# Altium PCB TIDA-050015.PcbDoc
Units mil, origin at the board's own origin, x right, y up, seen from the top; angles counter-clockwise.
Board outline 1539 x 1310 mil, 4 copper layers (Top Layer, Signal Layer 1, Signal Layer 2, Bottom Layer), stack 61.6 mil thick; 64 components, 25 nets, 161 pads, 163 vias.
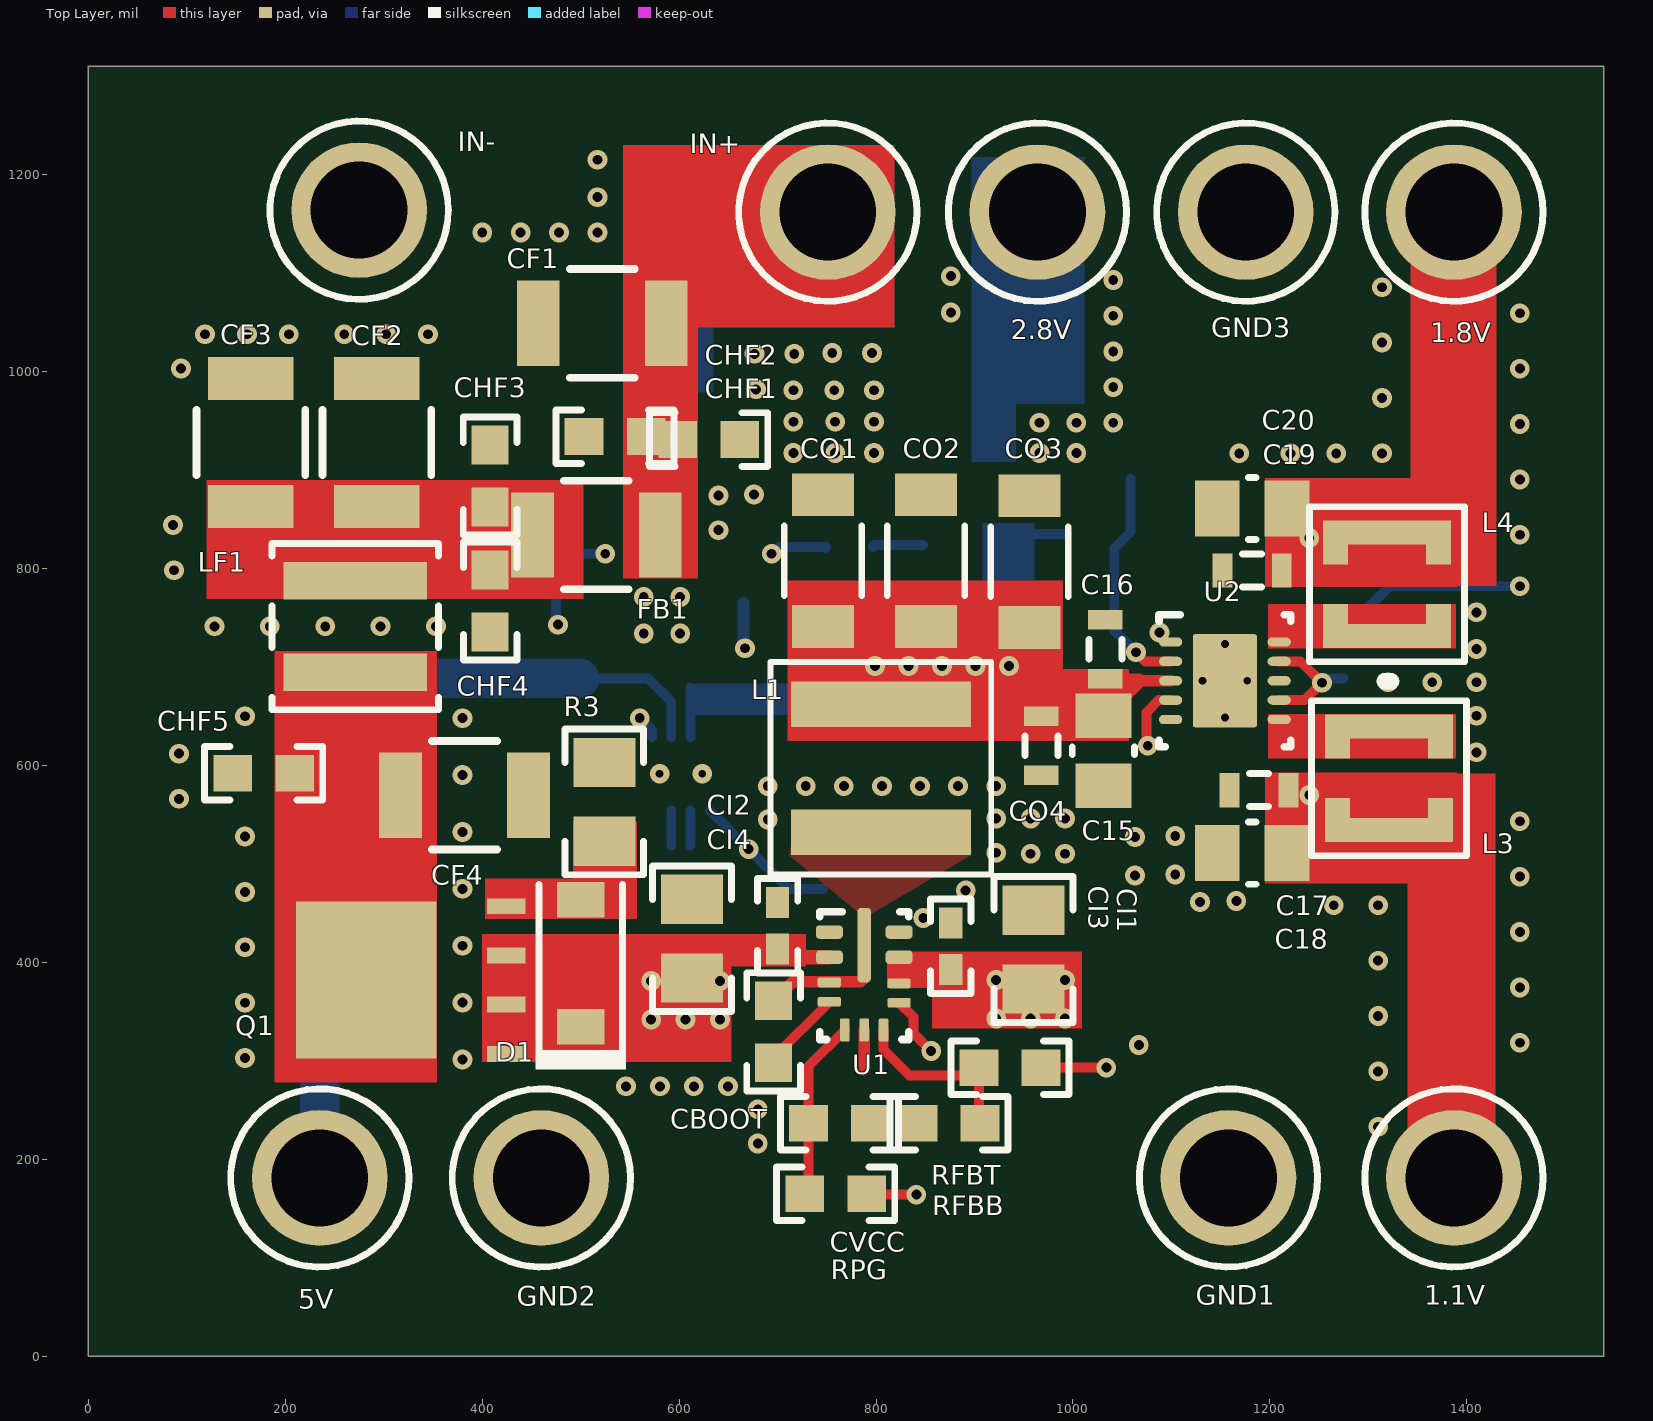
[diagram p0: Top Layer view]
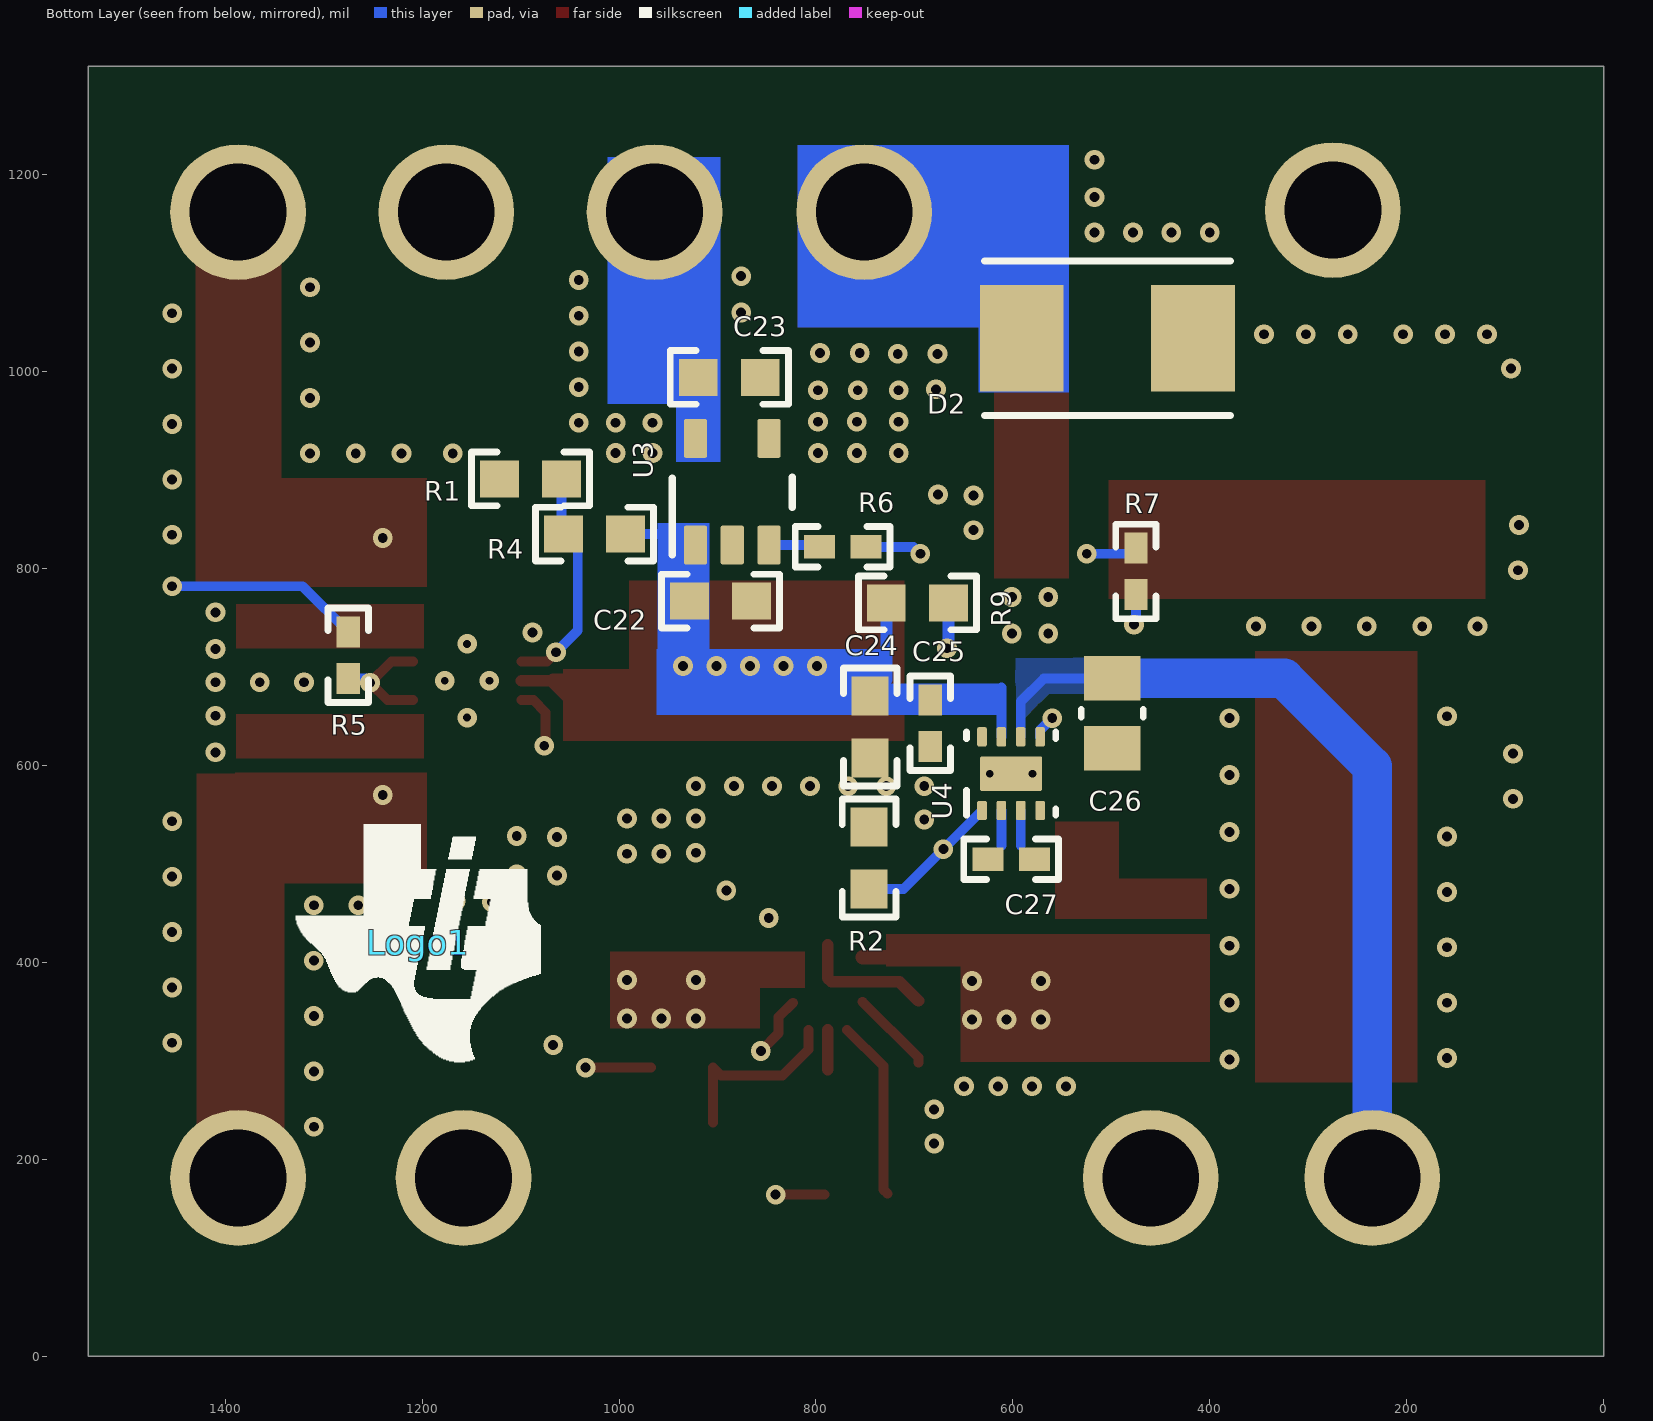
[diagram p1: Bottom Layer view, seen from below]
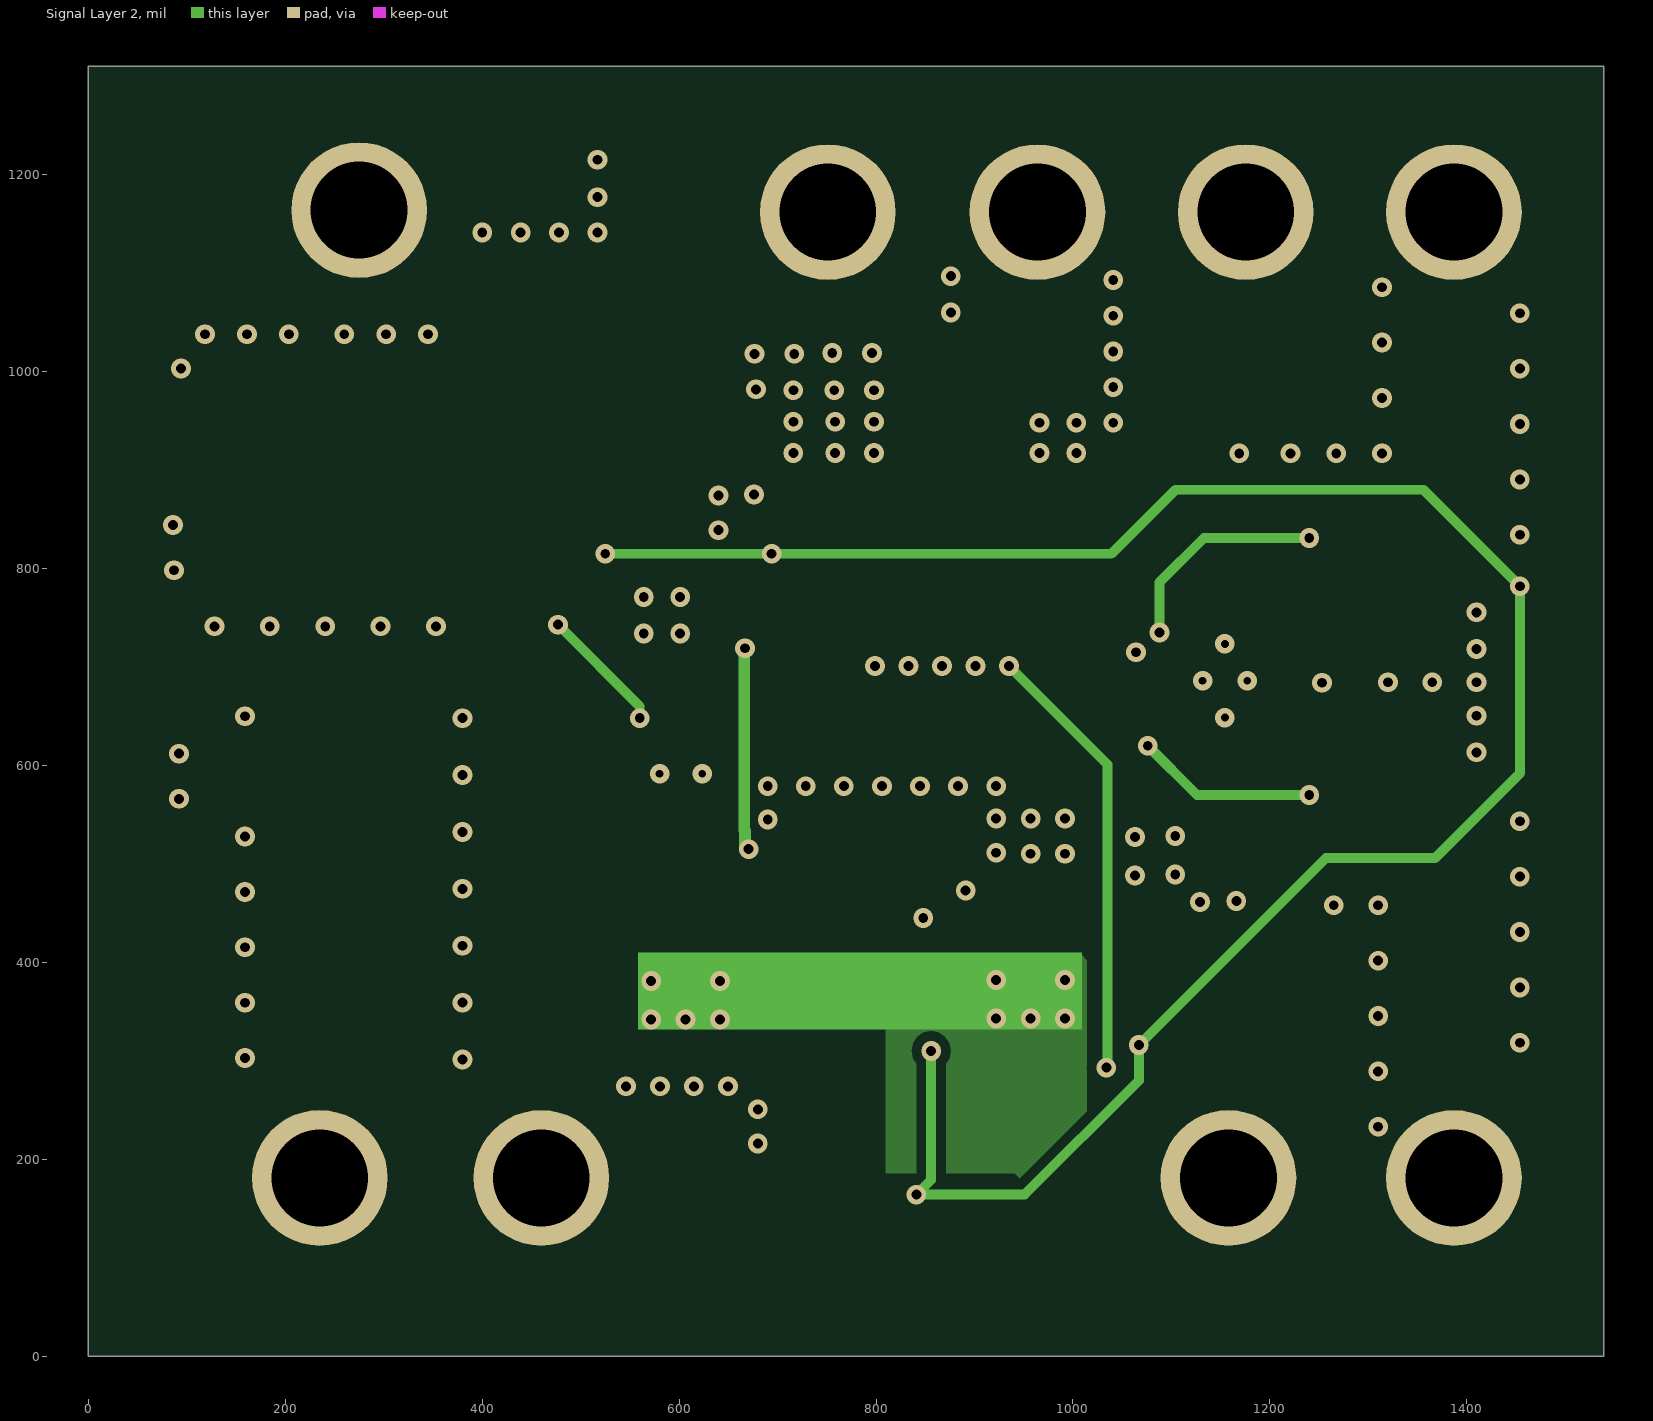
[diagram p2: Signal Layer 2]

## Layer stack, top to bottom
Top Solder: solder mask 0.4, Solder Resist, Dk 3.5
Top Layer: signal copper 1.4
Dielectric 1: prepreg 8, FR-4, Dk 4.2
Signal Layer 1: signal copper 1.4
Dielectric 2: core 40, FR-4, Dk 4.2
Signal Layer 2: signal copper 1.4
Dielectric 3: prepreg 8, FR-4, Dk 4.2
Bottom Layer: signal copper 1.4
Bottom Solder: solder mask 0.4, Solder Resist, Dk 3.5

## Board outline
0,0 1539,0 1539,1310 0,1310

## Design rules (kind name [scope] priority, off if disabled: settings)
AcuteAngle [All] p1: minimum=4.50000000000000E+0001 checktracksonly=FALSE
AssemblyTestPointUsage [All] p1: valid=2
BoardOutlineClearance BoardOutlineClearance_MountingHoles [OnCopper and InComponentClass('Mounting Holes')] p1: gap=40
BoardOutlineClearance BoardOutlineClearance_Poly [OnCopper and IsPoly] p2: gap=25
BoardOutlineClearance [OnCopper and Not InComponentClass('Logo') and not InComponentClass('FiducialMark') and not InRegion(1000,500,4000,800) and not InPoly] p3: gap=75
Clearance Clearance_Keepouts [((IsTrack Or IsArc) And Not InPoly) And IsFree and IsKeepOut vs ((IsTrack Or IsArc) And Not InPoly) And IsFree and IsKeepOut] p1: gap=0
Clearance Clearance_Poly [InPolygon] p2: gap=10
Clearance [All] p3: gap=7.87
ComponentClearance ComponentClearance_MountingHoles_FiducialMarks [InComponentClass('Mounting Holes') vs InComponentClass('FiducialMark')] p1: gap=50 collisioncheckmode=3 verticalgap=10 showdistances=FALSE
ComponentClearance ComponentClearance_Shunt [InComponentClass('Header') vs InComponentClass('Shunt')] p2: gap=0 collisioncheckmode=3 verticalgap=0 showdistances=FALSE
ComponentClearance ComponentClearance_Logo [InComponentClass('Logo')] p3: gap=50 collisioncheckmode=3 verticalgap=10 showdistances=FALSE
ComponentClearance ComponentClearance_ScrewToNut [(HasFootprint('NY PMS 440 0025 PH')) vs (HasFootprint('Keystone_1902C'))] p4: gap=5 collisioncheckmode=3 verticalgap=10 showdistances=FALSE
ComponentClearance ComponentClearance_MountingHoles [InComponentClass('Mounting Holes')] p5: gap=250 collisioncheckmode=3 verticalgap=100000 showdistances=FALSE
ComponentClearance ComponentClearance_SmallPassives [HasFootprint('0201*') or HasFootprint('0402*') or HasFootprint('0508') or HasFootprint('0603*') or HasFootprint('0612') or HasFootprint('0805*') or HasFootprint('0815*') or HasFootprint('0830*') or HasFootprint('1206*') or HasFootprint('1210*') or HasFootprint('1808*') or HasFootprint('1812*') or HasFootprint('1825*') or HasFootprint('2010*') or HasFootprint('2220*') or HasFootprint('2225*') or HasFootprint('2512*') or HasFootprint('2728*') or HasFootprint('3518*') vs HasFootprint('0201*') or HasFootprint('0402*') or HasFootprint('0508') or HasFootprint('0603*') or HasFootprint('0612') or HasFootprint('0805*') or HasFootprint('0815*') or HasFootprint('0830*') or HasFootprint('1206*') or HasFootprint('1210*') or HasFootprint('1808*') or HasFootprint('1812*') or HasFootprint('1825*') or HasFootprint('2010*') or HasFootprint('2220*') or HasFootprint('2225*') or HasFootprint('2512*') or HasFootprint('2728*') or HasFootprint('3518*')] p6: gap=14.96 collisioncheckmode=3 verticalgap=10 showdistances=FALSE
ComponentClearance ComponentClearance_THtoSMT [IsThruComponent vs IsSMTComponent] p7: gap=40 collisioncheckmode=3 verticalgap=30 showdistances=FALSE
ComponentClearance ComponentClearance_THtoTH [IsThruComponent vs IsThruComponent] p8: gap=30 collisioncheckmode=3 verticalgap=30 showdistances=FALSE
ComponentClearance [All] p9: gap=30 collisioncheckmode=3 verticalgap=10 showdistances=FALSE
DiffPairsRouting [All] p1: maxlimit=100 minlimit=10 mostfreqgap=10 toplayer_minwidth=15 toplayer_maxwidth=15 toplayer_prefwidth=15 midlayer1_minwidth=15 midlayer1_maxwidth=15 midlayer1_prefwidth=15 midlayer2_minwidth=15 midlayer2_maxwidth=15 midlayer2_prefwidth=15 bottomlayer_minwidth=15 bottomlayer_maxwidth=15 bottomlayer_prefwidth=15 maxuncoupledlength=1000
FabricationTestPointUsage TestPointUsage [All] p1: valid=2 allowmultiple=FALSE
FabricationTestpoint Testpoint [All] p1: side=3 testpointundercomponent=TRUE minsize=40 maxsize=100 preferedsize=60 minholesize=0 maxholesize=40 preferedholesize=32 testpointgrid=1 allowsidetop=TRUE allowsidebottom=TRUE usegrid=TRUE gridtolerance=0.01
FanoutControl Fanout_LCC [IsLCC] p1: bgadir=Out bgaviamode=Centered fanoutstyle=Auto fanoutdirection=Alternating viagrid=1 // Fanout_LCC (Default Rule)
FanoutControl Fanout_BGA [IsBGA] p2: bgadir=Out bgaviamode=Centered fanoutstyle=Auto fanoutdirection=Alternating viagrid=1 // Fanout_BGA (Default Rule)
FanoutControl Fanout_Default [All] p4: bgadir=Out bgaviamode=Centered fanoutstyle=Auto fanoutdirection=Alternating viagrid=1 // Fanout_Default (Default Rule)
FanoutControl Fanout_Small [(CompPinCount < 5)] p5: bgadir=Out bgaviamode=Centered fanoutstyle=Auto fanoutdirection=OutThenIn viagrid=1 // Fanout_Small (Default Rule)
HoleSize [All] p1: absolutevalues=TRUE maxlimit=251 minlimit=7.87 maxpercent=80.000 minpercent=20.000
MinimumAnnularRing MinimumAnnularRing_ThermalPadVias [IsVia and InAnyComponent] p1: minimumring=5.91
MinimumAnnularRing [All] p2: minimumring=8
MinimumSolderMaskSliver MinimumSolderMaskSliver_Logo [InComponentClass('Logo') vs InComponentClass('Logo')] p1: minsoldermaskwidth=0.7
MinimumSolderMaskSliver [All] p2: minsoldermaskwidth=3.94
PlaneConnect [All] p1: planeconnectstyle=Relief reliefexpansion=10 reliefentries=4 reliefconductorwidth=10 reliefairgap=10
PolygonConnect [All] p1: connectstyle=Direct reliefconductorwidth=10 reliefentries=4 polygonreliefangle="90 Angle" airgapwidth=10
RoutingVias ThermalPadVias [IsVia and InAnyComponent] p1: holewidth=7.87 width=19.68 viastyle="Through Hole" minholewidth=7.87 minwidth=19.68 maxholewidth=12.99 maxwidth=23.62
RoutingVias [All] p2: holewidth=16 width=34 viastyle="Through Hole" minholewidth=7.87 minwidth=26 maxholewidth=40 maxwidth=65
SilkToBoardRegionClearance [Not ((IsComment or IsDesignator) And (Hide <> 'False')) and not InRegion(1000,500,4000,800)] p1:
SilkToSilkClearance SilkToSilkClearance_Pb-FreeLogo [(HasFootprint('Pb-Free_Overlay_Medium') OR HasFootprint('Pb-Free_Overlay_Small')) vs (HasFootprint('Pb-Free_Overlay_Medium') OR HasFootprint('Pb-Free_Overlay_Small'))] p1: silktosilkclearance=0
SilkToSilkClearance [All] p2: silktosilkclearance=4
SilkToSolderMaskClearance SilkToComponentPadClearance [(IsPad or IsFill or IsRegion) and InAnycomponent] p1: minsilkscreentomaskgap=5 clearancetoexposedcopper=TRUE
SilkToSolderMaskClearance "Silk to Solder Mask Opening" [All] p2: minsilkscreentomaskgap=4 clearancetoexposedcopper=FALSE
SolderMaskExpansion [All] p1: expansion=1.97
Width [All] p1: maxlimit=100 minlimit=6 preferedwidth=10 checkconnectedcopper=TRUE
15 further rules are at their usual default settings.

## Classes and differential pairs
component class Logo: Logo1

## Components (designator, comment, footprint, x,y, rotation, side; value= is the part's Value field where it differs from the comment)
1.1V "Suggest using a net name here" Keystone1502-2 1387,181 r90 top
1.8V "Suggest using a net name here" Keystone1502-2 1387,1162 r90 top
2.8V "Suggest using a net name here" Keystone1502-2 964,1162 r90 top
5V "Suggest using a net name here" Keystone1502-2 235,181 r90 top
C15 "C2012X5R1A106M125AB" 0805_150 1031,615 r270 top
C16 "GCM188R71C104KA37J" 0603S 1033,718 r90 top
C17 "GCM188R71C104KA37J" 0603S 1189,575 r180 top
C18 "C2012X5R1A106M125AB" 0805_150 1182,511 r180 top
C19 "GCM188R71C104KA37J" 0603S 1182,798 r180 top
C20 "C2012X5R1A106M125AB" 0805_150 1182,861 r180 top
C22 "C0603C105K8PACTU" 0603 897,767 r0 bottom
C23 "GRM188R60J105KA01D" 0603 888,994 r180 bottom
C24 "C1608X5R1A106M080AC" 0603 745,639 r270 bottom
C25 "CL05A106MP5NUNC" 0402 684,643 r90 bottom
C26 "C2012X5R1A106M125AB" 0805_150 499,653 r270 bottom
C27 "C1005JB1V105K050BC" 0402 601.84,504.6 r0 bottom
CBOOT "0603YC104JAT2A" 0603 696,329.46 r90 top
CF1 "CGA6P3X7R1H475M250AB" 1210_280 522,1049 r180 top
CF2 "CGA6P3X7R1H475M250AB" 1210_280 293,928 r90 top
CF3 "CGA6P3X7R1H475M250AB" 1210_280 165,928 r90 top
CF4 "CGA6P3X7R1H475M250AB" 1210_280 382,569.74 r0 top
CHF1 "CGJ3E2X7R1C104K080AA" 0603 535,934 r180 top
CHF2 "CGJ3E2X7R1C104K080AA" 0603 630,931 r0 top
CHF3 "CGJ3E2X7R1C104K080AA" 0603 408,894 r90 top
CHF4 "CGJ3E2X7R1C104K080AA" 0603 408,767 r270 top
CHF5 "CGJ3E2X7R1C104K080AA" 0603 178,592 r180 top
CI1 "0805YD225KAT2A" 0805_HV 960,413 r90 top
CI2 "0805YD225KAT2A" 0805_HV 613,424 r270 top
CI3 "0402ZC103KAT2A" 0402 876,416.46 r90 top
CI4 "0402ZC103KAT2A" 0402 700,437 r90 top
CO1 "GRM31CR71A226KE15L" 1206_180 746,808 r270 top
CO2 "GRM31CR71A226KE15L" 1206_180 850.93,808 r270 top
CO3 "GRM31CR71A226KE15L" 1206_180 955.87,807 r270 top
CO4 "GCM188R71C104KA37J" 0603S 968,620 r270 top
CVCC "06033C105KAT2A" 0603 763,236.46 r0 top
D1 "MMSZ4705T1G" SOD-123 500,399 r90 top
D2 "1SMB30CAT3G" SMB-Bi 504,1034 r0 bottom
FB1 "FBMH3225HM601NT" 1210_280 516,834 r180 top
GND1 "Suggest using a net name here" Keystone1502-2 1158,181 r90 top
GND2 "Suggest using a net name here" Keystone1502-2 460,181 r90 top
GND3 "Suggest using a net name here" Keystone1502-2 1175.5,1162 r90 top
IN+ "Suggest using a net name here" Keystone1502-2 751,1162 r0 top
IN- "Suggest using a net name here" Keystone1502-2 275,1164 r0 top
L1 "XAL5030-222MEB" XAL5030 805,597 r90 top
L3 "LPS3015-222MLB" LPS3015 1321,587 r270 top
L4 "LPS3015-222MLB" LPS3015 1319,784 r90 top
LF1 "XAL4020-102MEB" XAL4020 271,741 r270 top
Logo1 "Texas Instruments" TI_Symbol_Overlay_Medium 1204,420 r180 bottom
Q1 "SQJ463EP-T1-GE3" PowerPAK_SO-8L 314,382 r180 top
R1 "CRCW06030000Z0EA" 0603 1090,891 r180 bottom
R2 "CRCW06030000Z0EA" 0603 746,506 r90 bottom
R3 "CRCW0805100KFKEA" 0805_HV 524,563 r270 top
R4 "CRCW06031M00FKEA" 0603 1025,835 r180 bottom
R5 "RC0402JR-070RL" 0402 1275,712 r270 bottom
R6 "RC0402JR-070RL" 0402 773,822 r0 bottom
R7 "RC0402JR-070RL" 0402 475,797 r270 bottom
R9 "CRCW06030000Z0EA" 0603 697,765 r180 bottom
RFBB "CRCW060334K8FKEA" 0603 874,236.46 r0 top
RFBT "CRCW0603100KFKEA" 0603 936,293 r0 top
RPG "CRCW0603100KFKEA" 0603 759,165 r0 top
U1 "LMR33630CRNXR" RNX0012A 788,386.46 r0 top
U2 "TPS62420DRCR" DRC0010J 1154.36,686 r0 top
U3 "LP5907MFX-2.8/NOPB" DBV0005A_N 885,878 r90 bottom
U4 "LM2775DSGR" DSG0008A 601.84,591.6 r90 bottom

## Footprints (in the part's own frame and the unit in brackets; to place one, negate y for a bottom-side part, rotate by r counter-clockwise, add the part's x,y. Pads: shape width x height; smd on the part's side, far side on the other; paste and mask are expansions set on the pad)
0402 [mm] "0402 from SM-752 data"
  rect 0.8x0.6 smd: 1(-0.6,0) 2(0.6,0)
  silkscreen extent -1.22,-0.52 1.22,0.52, body extent -0.55,-0.3 0.55,0.3, height 0.6
0603 [mm] "0603 from SM-752 data"
  rect 1x0.95 smd: 1(-0.8,0) 2(0.8,0)
  silkscreen extent -1.52,-0.69 1.52,0.69, body extent -0.87,-0.47 0.87,0.47, height 1
0603S [mil]
  rect 20x35 smd: 1(-30,0) 2(30,0)
  silkscreen extent -10,-17 10,17, body extent -34,-19 34,19, height 39
0805_150 [mm] "0805 / 1.5 mm height"
  rect 1.15x1.45 smd: 1(-0.9,0) 2(0.9,0)
  silkscreen extent -0.1,-0.8 0.1,0.8, body extent -1.1,-0.72 1.1,0.72, height 1.5
0805_HV [mil] "0805 with 30mil clearance between pads"
  rect 50x63 smd: 1(-40,0) 2(40,0)
  silkscreen extent -74,-40 74,40, body extent -43,-29 43,29, height 57
1206_180 [mm] "1206_180"
  rect 1.1x1.6 smd: 1(-1.7,0) 2(1.7,0)
  silkscreen extent -0.9,-1 0.9,1, body extent -1.75,-0.95 1.75,0.95, height 1.8
1210_280 [mm] "SMD, 2-Leads, Body 3.6x2.8mm, Height 2.8mm"
  rect 1.1x2.2 smd: 1(-1.65,0) 2(1.65,0)
  silkscreen extent -0.84,-1.4 0.84,1.4, body extent -1.8,-1.4 1.8,1.4, height 2.8
DBV0005A_N [mm] "SOT23, 5-Leads, Body 2.9x1.6mm, Pitch 0.95mm, Lead Span 2.8mm, IPC Medium Density"
  rrect17% 1x0.6 smd: 1(-1.375,0.95) 2(-1.375,0) 3(-1.375,-0.95) 4(1.375,-0.95) 5(1.375,0.95)
  silkscreen extent -1.63,-1.55 0.38,1.55, body extent -1.42,-1.46 1.42,1.46, height 1.09
DRC0010J [mm] "SON, 10-Leads, Body 3x3mm, Pitch 0.5mm, Thermal Pad 2.4x1.65mm, TI Recommended"
  rrect100% 0.6x0.24 smd: 1(-1.4,1) 2(-1.4,0.5) 3(-1.4,0) 4(-1.4,-0.5) 5(-1.4,-1) 6(1.4,-1) 7(1.4,-0.5) 8(1.4,0) 9(1.4,0.5) 10(1.4,1)
  rrect6% 1.65x2.4 smd paste-0.825: 11(0,0)
  silkscreen extent -1.7,-1.7 1.7,1.7, body extent -1.55,-1.55 1.55,1.55, height 1.01
DSG0008A [mm] "SON, 8-Leads, Body 2x2mm, Pitch 0.5mm, Thermal Pad 1.6x0.9mm, TI Recommended"
  rrect40% 0.5x0.25 smd: 1(-0.95,0.75) 2(-0.95,0.25) 3(-0.95,-0.25) 4(-0.95,-0.75) 5(0.95,-0.75) 6(0.95,-0.25) 7(0.95,0.25) 8(0.95,0.75)
  rrect14% 0.9x0.7 on Bottom Paste: 9(0,-0.45) 9(0,0.45)
  rrect11% 0.9x1.6 smd paste-0.45: 9(0,0)
  silkscreen extent -1.07,-1.15 1.07,1.15, body extent -1,-1 1,1, height 0.77
Keystone1502-2 [mm] "Double Turret"
  round 3.5 hole 2.5: 1(0,0)
  silkscreen extent -2.3,-2.3 2.3,2.3, body extent -1.6,-1.6 1.59,1.6, height 5.62
LPS3015 [mm] "Coilcraft recommended land pattern.  Document 436-2, rev 12/3/08"
  rect 0.63x3.3 smd: 1(-1.335,0) 2(1.335,0)
  rect 1.14x0.64 smd: 1(-1.08,1.33) 1(-1.08,-1.33) 2(1.08,1.33) 2(1.08,-1.33)
  silkscreen extent -2.59,-2 2,2, body extent -1.58,-1.58 1.58,1.58, height 1.52
PowerPAK_SO-8L [mm] "based on Vishay recommended land pattern Document 63818 Feb 7, 2012"
  rect 1x0.41 smd: 1(-2.805,1.905) 2(-2.805,0.635) 3(-2.805,-0.635) 4(-2.805,-1.905)
  rect 3.63x4.061 smd: 5(0.805,0)
  Top Layer region: -0.298,-2.64 0.298,-2.64 0.298,-2.03 -0.298,-2.03
  Top Layer region: -0.297,2.03 0.298,2.03 0.298,2.64 -0.297,2.64
  Top Layer region: 2.615,-2.5 3.125,-2.5 3.125,2.5 2.615,2.5
  body extent -3.07,-2.57 3.08,2.57, height 1.21
RNX0012A [mm]
  rrect57% 0.7x0.35 smd paste-0.05 mask-0.05: 1(-0.9,1.125) 2(-0.9,0.475) 10(0.9,0.475) 11(0.9,1.125)
  rrect40% 0.6x0.25 smd: 3(-0.9,-0.175) 4(-0.9,-0.675) 8(0.9,-0.7) 9(0.9,-0.2)
  rrect40% 0.25x0.6 smd: 5(-0.5,-1.4) 6(0,-1.4) 7(0.5,-1.4)
  rrect40% 0.25x0.812 on Top Paste: 12(0,0.28) 12(0,1.295)
  rrect57% 0.35x1.925 smd paste-0.175 mask-0.05: 12(0,0.788)
  silkscreen extent -1.15,-1.65 1.15,1.65, body extent -1.05,-1.55 1.05,1.55, height 1.02
SMB-Bi [mil] "Molded Diode, 2-Leads, Body 5.4x3.6mm, IPC Medium Density, based on OnSemi component dimensions"
  rect 85x107.99 smd: 1(-87.01,0) 2(87.01,0)
  silkscreen extent -125,-79 125,79, body extent -104,-73 104,73, height 89
SOD-123 [mm] "On Semi recommended land pattern"
  rect 0.915x1.22 smd: 1(-1.637,0) 2(1.637,0)
  silkscreen extent -2.74,-1.17 2.03,1.17, body extent -1.93,-0.9 1.93,0.9, height 1.35
TI_Symbol_Overlay_Medium [mil]
  silkscreen extent -124,-122 124,120
XAL4020 [mil] "Coilcraft XAL4020 7/18/12"
  rect 38x146 smd: 1(-46.5,0) 2(46.5,0)
  silkscreen extent -85,-85 85,85, body extent -84,-84 84,84, height 83
XAL5030 [mil] "Coilcraft XAL5030 12/12/11"
  rect 46x183 smd: 1(-65,0) 2(65,0)
  silkscreen extent -108,-112 108,112, body extent -108,-112 108,112, height 122

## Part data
1.1V 1.8V 2.8V 5V GND1 GND2 GND3 IN+ IN-: library part 1502-2, "Terminal, Turret, TH, Double"
C15 C18 C20 C26: "CAP, CERM, 10 µF, 10 V,+/- 20%, X5R, 0805"
C16 C17 C19 CHF1 CHF2 CHF3 CHF4 CHF5 CO4: "CAP, CERM, 0.1 µF, 16 V, +/- 10%, X7R, AEC-Q200 Grade 1, 0603"
C22: "CAP, CERM, 1 µF, 10 V,+/- 10%, X5R, 0603"
C23: "CAP, CERM, 1 µF, 6.3 V,+/- 10%, X5R, 0603"
C24: "CAP, CERM, 10 µF, 10 V,+/- 20%, X5R, 0603"
C25: "CAP, CERM, 10 µF, 10 V,+/- 20%, X5R, 0402"
C27: "CAP, CERM, 1 µF, 35 V,+/- 10%, JB, 0402"
CBOOT: "CAP, CERM, 0.1 µF, 16 V,+/- 5%, X7R, 0603"
CF1 CF2 CF3 CF4: "CAP, CERM, 4.7 µF, 50 V, +/- 20%, X7R, AEC-Q200 Grade 1, 1210"
CI1 CI2: "CAP, CERM, 2.2 µF, 16 V,+/- 10%, X5R, 0805"
CI3 CI4: "CAP, CERM, 0.01 µF, 10 V,+/- 10%, X7R, 0402"
CO1 CO2 CO3: "CAP, CERM, 22 µF, 10 V, +/- 10%, X7R, 1206"
CVCC: "CAP, CERM, 1 µF, 25 V,+/- 10%, X7R, 0603"
D1: "Diode, Zener, 18 V, 500 mW, SOD-123"
D2: "Diode, TVS, Bi, 30 V, 48.4 Vc, SMB"
FB1: "Ferrite Bead, 600 ohm @ 100 MHz, 3 A, 1210"
L1: "Inductor, Shielded, Composite, 2.2uH, 9.2A, 0.01 ohm, SMD"
L3 L4: "Inductor, Shielded Drum Core, Ferrite, 2.2uH, 1.4A, 0.11 ohm, SMD"
LF1: "Inductor, Shielded, Composite, 1uH, 8.75A, 0.01 ohm, SMD"
Logo1: library part TI_Logo, "Texas Instrument Corporate Signature"
Q1: "MOSFET, P-CH, -40 V, -30 A, PowerPAK_SO-8L"
R1 R2 R9: "RES, 0, 5%, 0.1 W, 0603"
R3: "RES, 100 k, 1%, 0.125 W, 0805"
R4: "RES, 1.00 M, 1%, 0.1 W, 0603"
R5 R6 R7: "RES, 0, 5%, 0.063 W, 0402"
RFBB: "RES, 34.8 k, 1%, 0.1 W, 0603"
RFBT RPG: "RES, 100 k, 1%, 0.1 W, 0603"
U1: "SIMPLE SWITCHER 3.8V to 36V 3A/2A Synchronous Step-Down Voltage Regulator, RNX0012A (VQFN-HR-12)"
U2: "Buck Adjustable Regulator with 2.5 to 6 V Input and 0.6 to 6 V Output, -40 to 85 degC, 10-Pin SON (DRC), Green (RoHS & no Sb/Br)"
U3: "250-mA Ultra-Low-Noise, Low-IQ LDO, DBV0005A (SOT-23-5)"
U4: "Switched Capacitor 5V Boost Converter, DSG0008A (WSON-8)"

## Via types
v1: diameter 20, hole 10, Top Layer to Bottom Layer, tented both sides, 144 vias
v2: diameter 20, hole 10, Top Layer to Bottom Layer, 13 vias
v3: diameter 19.68, hole 7.87, Top Layer to Bottom Layer, 6 vias

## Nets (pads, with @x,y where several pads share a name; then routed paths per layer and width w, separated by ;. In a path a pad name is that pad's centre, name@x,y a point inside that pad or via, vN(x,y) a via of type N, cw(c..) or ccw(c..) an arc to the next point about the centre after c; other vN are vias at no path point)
1.1V: 1.1V.1 C17.1 C18.1 L3.2 U2.4 | length 247
  Top Layer w10: v2@1074.56,621.44 1074.56,653.92 1086.95,666.32 U2.4
  Signal Layer 2 w10: v2(1076,620) 1126,570 v1(1240,570)
1.8V: 1.8V.1 C19.1 C20.1 L4.2 U2.1 | length 223.1
  Signal Layer 2 w10: v2@1089,734 v2(1088,735) 1088,786 1133,831 v1(1240,831)
3.3V: C15.1 C16.1 C22.2 C24.1 C25.2 CO1.2 CO2.2 CO3.2 CO4.1 L1.2 R4.2 R9.1 RFBT.2 U2.3 U3.1 U4.7 | length 828.1
  Top Layer w10: RFBT.2 v2(1034,293)
  Top Layer w12: 1066.57,686 U2.3
  Top Layer w15: C15.1 1066.57,686 C16.1@1035,686
  Signal Layer 2 w10: v1(935,701) 1035,601 1035,300 v2@1031,296
  Bottom Layer w10: U4.7 611.69,679.31 ; v1(799,701) 809,691 ; 937,835 R4.2
  Bottom Layer w12: C24.1@728.5,687 R9.1
  other v1: 833,701 867,701 901,701
5V: 5V.1 C26.1 U4.6 | length 857.8
  Bottom Layer w10: C26.1 568.57,688.43 592,665 U4.6
  Bottom Layer w40: 5V.1 235,599 324.43,688.43 C26.1
FB: RFBB.2 RFBT.1 U1.7 | length 186.6
  Top Layer w10: U1.7 807.68,311.32 834,285 896.5,285 RFBT.1 RFBB.2@904.5,237.45
GND: C15.2 C16.2 C17.2 C18.2 C19.2 C20.2 C22.1 C23.2 C24.2 C25.1 C26.2 CF1.2 CF2.2 CF3.2 CF4.2 CHF1.2 CHF2.2 CHF3.2 CHF4.2 CHF5.2 CI1.2 CI2.1 CI3.2 CI4.2 CO1.1 CO2.1 CO3.1 CO4.2 CVCC.2 D2.1 GND1.1 GND2.1 GND3.1 IN-.1 R1.1 R2.2 R3.1 RFBB.1 U1.1 U1.6 U1.11 U2.5 U2.8 U2.11 U3.2 U4.4 U4.8 U4.9@601.84,591.6 | length 40.3
  Top Layer w12: 788,291 U1.6
  other v1: 680,216 1310,233 680,250.67 546,274 580.67,274 615,274 649.67,274 1310,289.25 380,301.25 159,302.75 1454,318.25 1310,345.5 159,359 380,359.04 1454,374.5 1310,401.75 159,415.25 380,416.83 1454,430.75 848,445 1265,458 1310,458 1129,461.25 1166,462.25 159,471.5 891,473 380,474.62 1454,487 1063,488.25 1104,489.25 957,510.33 992,510.33 922,511.33 1063,527.25 159,527.75 1104,528.25 380,532.42 1454,543.25 690,545 922,546 957,546 992,546 92,566 690,579 728.67,579 767.33,579 806,579 844.67,579 883.33,579 922,579 380,590.21 92,612 1410,613.25 380,648 159,650 1410,650.5 1320,684.5 1365,684.5 1410,684.5 1410,718.25 564,734 601,734 128,741.25 184.25,741.25 240.5,741.25 296.75,741.25 353,741.25 1410,755.5 564,771 601,771 87,798.25 1454,834.25 640,839 86,844.25 640,874.25 676,875.25 1454,890.5 716,917.25 758.5,917.25 798,917.25 966,917.25 1003.5,917.25 1169,917 1221,917 1267.5,917 1314,917 1454,946.75 966,948 1003.5,948 1041,948 716,949.12 758.5,949.12 798,949.12 1314,973.25 716,981 757.5,981 798,981 678,982 1041,984.25 94,1003.25 1454,1003 676.5,1018 717,1018 755.5,1019 796,1019 1041,1020.5 1314,1029.5 118.4,1038 161,1038 203.6,1038 259.8,1038 302.4,1038 345,1038 1041,1056.75 1454,1059.25 876,1060 1314,1085.75 1041,1093 876,1097 400,1141.25 439,1141.25 478,1141.25 517,1141.25 517,1177.25 517,1215.25
  other v3: 580.19,591.6 623.5,591.6 1154.36,648.6 1131.72,686 1177,686 1154.36,723.4
MODE: R1.2 R4.1 U2.2 | length 231.1
  Top Layer w10: v2(1064,715) 1073.31,705.69 U2.2
  Bottom Layer w10: R1.2 1058.5,837.01 R4.1 1042,820.5 1042,737 v2(1064,715)
Net2.8V_1: 2.8V.1 C23.1 U3.5
NetC27_1: C27.1 U4.3 | length 35.8
  Bottom Layer w10: 592,518.38 U4.3
NetC27_2: C27.2 U4.2 | length 35.8
  Bottom Layer w10: 611.69,518.38 U4.2
NetCBOOT_1: CBOOT.1 U1.4 | length 85.4
  Top Layer w10: CBOOT.1 696,303.32 U1.4
NetCF1_1: CF1.1 CHF1.1 CHF2.1 D2.2 FB1.1 IN+.1
NetCF2_1: CF2.1 CF3.1 CHF3.1 CHF4.1 FB1.2 LF1.1
NetCF4_1: CF4.1 CHF5.1 LF1.2 Q1.5
NetD1_2: D1.2 Q1.4 R3.2 | length 69.1
  Top Layer w10: Q1.4 D1.2@493.53,457
NetL3_1: L3.1 U2.6
NetL4_1: L4.1 U2.10
NetR5_2: R5.2 U2.7 U2.9 | length 127.2
  Top Layer w10: U2.7 1235.32,666.32 v1(1253,684) 1231.31,705.69 U2.9
  Bottom Layer w10: v1(1253,684) 1257.38,688.38 R5.2
NetR6_2: R6.2 U3.3 | length 51.7
  Bottom Layer w10: R6.2 798.49,823.87 U3.3
NetR7_2: R7.2 U4.5 | length 181.9
  Signal Layer 2 w10: v2(477,743) 560,660 v2(560,648)
  Bottom Layer w10: v2@475,745 R7.2 ; v2(560,648) 572.32,635.68 U4.5
PFM: R2.1 R9.2 U4.1 | length 393.3
  Signal Layer 2 w12: v2@667,518.57 667,533.36 666.13,534.24 666.13,718.13 v2(667,719)
  Bottom Layer w10: U4.1 v2(670.57,515) 711.06,474.5 R2.1
  Bottom Layer w12: v2@665.5,720.5 R9.2
PG: R5.1 R6.1 R7.1 RPG.2 U1.8 | length 2572.2
  Top Layer w10: RPG.2@791.5,164 v2(841,164) ; U1.8 838,344.33 838,328 v2(856,310)
  Signal Layer 2 w10: v2(525,815) v2(694,815) 1039,815 1104,880 1356,880 v1(1454,782) 1454,592 1368,506 1257,506 v2(1067,316) 1067,280 951,164 v2(841,164) 856,179 v2(856,310)
  Bottom Layer w10: R7.1 480.62,815 v2(525,815) ; v2(694,815) 701,822 R6.1 R6.1@748.38,821 ; R5.1 1321.38,782 v1(1454,782)
SW: CBOOT.2 L1.1 U1.3 U1.12@788,417.48 | length 135
  Top Layer w12: CBOOT.2 715.22,380.18 784.18,380.18 788,384 U1.12@788,417.48
VCC: CVCC.1 RPG.1 U1.5 | length 183.2
  Top Layer w10: RPG.1 731.5,169 CVCC.1 731.5,294.53 U1.5
VIN: CI1.1 CI2.2 CI3.1 CI4.1 D1.1 Q1.1 Q1.2 Q1.3 U1.2 U1.9 U1.10 | length 118.4
  Top Layer w15: CI2.2@634.16,405.16 U1.2
  other v1: 571.54,342 606.54,342 641.54,342 922,343 957,343 992,343 571.54,381 641.54,381 922,382 992,382
pads on no net: U1.12@788,397.48 U1.12@788,437.44 U3.4 U4.9@584.13,591.6 U4.9@619.56,591.6

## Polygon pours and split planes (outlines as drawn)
SW on Top Layer "TOP_LAYER_SW_P020" (solid, remove dead copper, pour order 20): 788.5,445.5 712,509 714,520 897.5,523 897.5,514.5 896,509
5V on Bottom Layer "BOTTOM_LAYER_5V_P022" (solid, remove dead copper, pour order 22): 471,711 472,710 597,709 599,641 597,639 563,673 561,673 469,673 471,675
VIN on Signal Layer 2 "SIGNAL_LAYER_2_VIN_P034" (solid, remove dead copper, pour order 34): 823,409 1008,409 1009,410 1014,405 1014,257 1014,243 949,178 941,186 810,186 810,399 820,409

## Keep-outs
Keep-Out Layer:
  text ".Layer_Name" at 577,-858.49 h60

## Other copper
Top Layer:
  rectangle net 1.1V: 1340,133 1429,592
  rectangle net 1.8V: 1343,782 1430,1215
  rectangle net NetCF1_1: 543,790 619,1118
  rectangle net NetCF1_1: 543,1045 819,1230
  rectangle net NetCF2_1: 120,769 503,890
  rectangle net NetCF4_1: 189,278 354,716
  rectangle net VIN: 400,299 653,429
  rectangle net VIN: 581,396 729,429
  rectangle net VIN: 811,374 997,411
  rectangle net NetL4_1: 1198,719 1389,764
  rectangle net NetL3_1: 1198,607 1389,652
  rectangle net 1.1V: 1195,480 1390,593
  rectangle net 1.8V: 1195,781 1390,892
  rectangle net VIN: 857,333 1009,411
  rectangle net NetD1_2: 492,444 557,543
  rectangle net NetD1_2: 403,444 557,485
  rectangle net 3.3V: 710,625 990,788
  rectangle net 3.3V: 924,625 1057,698
  text ".Layer_Name" at 577,-858.49 h60
Signal Layer 2:
  rectangle net VIN: 558,332 1009,410
Bottom Layer:
  rectangle net NetCF1_1: 543,979 635,1146
  rectangle net NetCF1_1: 543,1045 819,1230
  rectangle net Net2.8V_1: 897,967 1012,1218
  rectangle net Net2.8V_1: 897,908 942,1015
  rectangle net 3.3V: 908,662 961,846
  rectangle net 3.3V: 726,651 962,718
  rectangle net 3.3V: 609,651 753,683
  text ".Layer_Name" at 577,-858.49 h60

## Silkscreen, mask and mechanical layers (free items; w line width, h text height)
Top Overlay:
  text ".Layer_Name" at 577,-858.49 h60
Bottom Overlay:
  text ".Layer_Name" at 577,-858.49 h60
Top Paste:
  text ".Layer_Name" at 577,-858.49 h60
Bottom Paste:
  text ".Layer_Name" at 577,-858.49 h60
Top Solder:
  text ".Layer_Name" at 577,-858.49 h60
  text ".Layer_Name" at 577,-858.49 h60
Bottom Solder:
  text ".Layer_Name" at 577,-858.49 h60
Drill Guide:
  text ".Layer_Name" at 577,-858.49 h60
M1 Board Outline:
  the board outline again, w10
  text ".Layer_Name" at 577,-858.49 h60
M2 Board Dimensions:
  rectangle: 125,-400 500,-275
  rectangle: 0,-275 125,-150
  lines w7: 0,-275 1000,-275 ; 125,-400 125,-150 ; 250,-400 250,-150 ; 500,-400 500,-150 ; 750,-400 750,-150 ; 0,-400 0,-150 1000,-150 1000,-400 0,-400
  text ".Layer_Name" at 577,-858.49 h60
M3 3D STEP Top:
  text ".Layer_Name" at 577,-858.49 h60
M4 3D STEP Bottom:
  text ".Layer_Name" at 577,-858.49 h60
M5 Assembly Top:
  lines w10: -292,-930.17 6308,-930.17 ; -292,-726.83 6310,-726.83 ; -292,-523.5 -292,-1133.5 3713,-1133.5 6310,-1133.5 6310,-523.5 -291.5,-523.5 -291.5,-1133.5 1284,-1133.5 ; 2173,-1133.5 2173,-523.5 ; 3440,-726.83 3440,-523.5 ; 4280,-726.83 4280,-523.5 ; 4902,-1140 4902,-937.17
  text "COMPONENTS MARKED 'DNP' SHOULD NOT BE POPULATED." at 1153.5,-318.5 h60
  text "ASSEMBLY VARIANT:" at 1153,-434 h60
  text ".VariantName" at 2189,-434 h60
  text "PCB VIEWED FROM TOP SIDE" at -228.5,-655.67 h60
  text "BOARD #:" at 2248,-655.67 h60
  text ".PRJ_Number" at 2793.5,-655.67 h60
  text "REV:" at 3638,-655.67 h60
  text ".PCB_Rev" at 3929.5,-655.67 h60
  text "SVN REV:" at 4476,-655.67 h60
  text ".VersionControl_RevNumber" at 4982,-655.67 h60
  text "TID #:" at 2248,-859 h60
  text ".TID" at 2793.5,-859 h60
  text "PLOT NAME =" at -228.5,-1064.34 h60
  text ".plot_File_Name" at 577,-1064.34 h60
  text "GENERATED    :" at 2250,-1064.34 h60
  text ".Print_Date" at 3119.5,-1064.34 h60
  text ".Print_Time" at 3848.5,-1064.34 h60
  text "TEXAS INSTRUMENTS" at 5113,-1064.34 h60
M6 Assembly Bottom:
  lines w10: -292.5,-727.33 6309.5,-727.33 ; -290.5,-930.67 6309.5,-930.67 ; 1115.5,-1140.5 1115.5,-937.67 ; 1737.5,-727.33 1737.5,-524 ; 2577.5,-727.33 2577.5,-524 ; 3844.5,-1134 3844.5,-524 ; 4733.5,-1134 6309,-1134 6309,-524 -292.5,-524 -292.5,-1134 2304.5,-1134 6309.5,-1134 6309.5,-524
  text "COMPONENTS MARKED 'DNP' SHOULD NOT BE POPULATED." at 6102,-318 h60
  text ".VariantName" at 5058,-434 h60
  text "ASSEMBLY VARIANT:" at 6097,-434 h60
  text ".VersionControl_RevNumber" at 1035.5,-656.17 h60
  text "SVN REV:" at 1541.5,-656.17 h60
  text ".PCB_Rev" at 2088,-656.17 h60
  text "REV:" at 2379.5,-656.17 h60
  text ".PRJ_Number" at 3224,-656.17 h60
  text "BOARD #:" at 3769.5,-656.17 h60
  text "PCB VIEWED FROM BOTTOM SIDE" at 6246,-656.17 h60
  text ".TID" at 3224,-859.5 h60
  text "TID #:" at 3769.5,-859.5 h60
  text "TEXAS INSTRUMENTS" at 904.5,-1064.84 h60
  text ".Print_Time" at 2169,-1064.84 h60
  text ".Print_Date" at 2898,-1064.84 h60
  text "GENERATED    :" at 3767.5,-1064.84 h60
  text ".plot_File_Name" at 5440.5,-1064.84 h60
  text "PLOT NAME =" at 6246,-1064.84 h60
M9 Title Sheet:
  drawing of 57 lines, arcs and shapes, not listed
  text "1" at 739.84,8036.5 h70
  text "2" at 3235.5,8036.5 h70
  text "3" at 5724.84,8036.5 h70
  text "4" at 8231.51,8036.5 h70
  text "5" at 10730.5,8036.5 h70
  text "6" at 13235.5,8036.5 h70
  text "A" at -416.5,6893.5 h70
  text "A" at 14383.5,6893.5 h70
  text "B" at -416.5,4513.5 h70
  text "B" at 14383.5,4513.5 h70
  text "C" at -416.5,2138.5 h70
  text "C" at 14383.5,2138.5 h70
  text "PROJECT TITLE:" at 11343.5,277.5 h45
  text ".PRJ_Title" at 11393.5,144.17 h70
  text "DESIGNED FOR:" at 11343.5,-23.5 h45
  text ".PRJ_Customer" at 11393.5,-163.5 h70
  text "D" at -416.5,-231.5 h70
  text "D" at 14383.5,-231.5 h70
  text "FILE NAME:" at 11343.5,-323.5 h45
  text ".PCB_File_Name_No_Path" at 11393.5,-443.5 h70
  text "Texas Instruments (TI) and/or its licensors do not warrant the accuracy or completeness of this specification" at 6374,-605.34 h45
  text "ENGINEER:" at 11343.5,-613.5 h45
  text "LAYOUT BY:" at 12848.5,-613.5 h45
  text "or any information contained therein. TI and/or its licensors do not warrant that this design will meet" at 6329.01,-718 h45
  text ".PRJ_Engineer" at 11393.5,-768.49 h70
  text ".PCB_Layout" at 12899,-768.49 h70
  text "the specifications, will be suitable for your application or fit for any particular purpose, or will operate in" at 6329.01,-830.67 h45
  text ".Layer_Name" at 577,-858.49 h60
  text "ALTIUM DESIGNER VERSION:" at 12848.5,-923.5 h45
  text "an implementation. TI and/or its licensors do not warrant that the design is production worthy. You should" at 6329.01,-943.33 h45
  text "completely validate and test your design implementation to confirm the system functionality for your application." at 6374,-1056 h45
  text ".print_Scale" at 11393.5,-1056.83 h70
  text ".Application_BuildNumber" at 12899,-1056.83 h70
  text "1" at 739.84,-1263.5 h70
  text "2" at 3235.5,-1263.5 h70
  text "3" at 5724.84,-1263.5 h70
  text "4" at 8231.51,-1263.5 h70
  text "5" at 10730.5,-1263.5 h70
  text "6" at 13235.5,-1263.5 h70
M10 Fab Notes:
  drawing of 173 lines, arcs and shapes, not listed
  text "DESIGN INFORMATION" at 12378.02,6201 h60
  text "MIN. TRACK WIDTH:" at 11733.46,6021 h60
  text "8" at 12829.7,6021 h60
  text "MIL" at 12984.46,6021 h60
  text "MIN. CLEARANCE:" at 11733.46,5889 h60
  text "0.2" at 12769.7,5889 h60
  text "mm" at 12984.46,5889 h60
  text "MIN. VIA PAD SIZE:" at 11733.46,5757 h60
  text "24" at 12799.71,5757 h60
  text "MIL" at 12984.46,5757 h60
  text "0.05mm (2MIL)" at 12428.46,5615.29 h60
  text "MINIMUM ANNULAR RING" at 11404.23,5611 h60
  text "EXTERNAL" at 13136.46,5611 h60
  text "PER" at 11604.23,5493 h60
  text "IPC-D-275 CLASS 2 LEVEL C" at 11824.23,5493 h60
  text "MIL, HOLES" at 13312.46,5380.71 h60
  text "+/-" at 12920,5380 h60
  text "+/-" at 13774,5380 h60
  text "REGISTRATION TOLERANCES:" at 11404.23,5375 h60
  text "METAL" at 12604,5375 h60
  text "5" at 13180.2,5375 h60
  text "3" at 14013.2,5375 h60
  text "MIL" at 14129.46,5375 h60
  text "+/-" at 13774,5262 h60
  text "HOLE SIZE TOLERANCE (UNLESS OTHERWISE SPECIFIED):" at 11404.23,5257 h60
  text "3" at 14013.2,5257 h60
  text "MIL" at 14129.46,5257 h60
  text "MATERIAL:" at 11329.46,5047.54 h60
  text "FR-4 High Tg" at 12315.9,4907.21 h60
  text "FR-408" at 11750.46,4898.64 h60
  text "OTHER" at 13238.46,4898.64 h60
  text "X" at 12161,4895 h60
  text "62 MIL (1.6mm) +/-10%" at 12070.56,4735.92 h60
  text "THICKNESS:" at 11404.23,4731.64 h60
  text "X" at 11942.4,4731.64 h60
  text "OTHER" at 13355.46,4731.64 h60
  text "TOLERANCE:" at 11404.23,4573.64 h60
  text "X" at 12243.53,4573.64 h60
  text "ANSI IPC-6012 TYPE 3 CLASS 2" at 12430.48,4573.64 h60
  text "OTHER +/-" at 12430.46,4417.64 h60
  text "BOW & TWIST:" at 11404.23,4260.64 h60
  text "X" at 12243.53,4260.64 h60
  text "ANSI IPC-6012 TYPE 3 CLASS 2" at 12430.48,4260.64 h60
  text "OTHER +/-" at 12430.46,4102.13 h60
  text "DRILLING:" at 11329.46,3963.64 h60
  text "REFERENCE:" at 11404.23,3846.64 h60
  text "X" at 12052.46,3846.64 h60
  text "AS SHOWN" at 12239.46,3846.64 h60
  text "X" at 12953.46,3846.64 h60
  text "NC_DRILL FILES" at 13090.46,3846.64 h60
  text "PTH COPPER THICKNESS:" at 11404.23,3688.64 h60
  text "X" at 12534.46,3688.64 h60
  text "20-30 um" at 12671.46,3688.64 h60
  text "OTHER" at 13388.46,3688.64 h60
  text "BOARD FINISH:" at 11329.46,3529.64 h60
  text "SILKSCREEN:" at 11484.68,3411.64 h60
  text "X" at 12433.46,3411.64 h60
  text "TOP" at 12559.46,3411.64 h60
  text "X" at 12943.46,3411.64 h60
  text "BOTTOM" at 13070.46,3411.64 h60
  text "SILKSCREEN COLOR:" at 11484.68,3244.64 h60
  text "X" at 12432.42,3244.64 h60
  text "WHITE" at 12559.46,3244.64 h60
  text "OTHER" at 13070.46,3244.64 h60
  text "X" at 12563.42,3085.44 h60
  text "GREEN" at 12690.46,3085.44 h60
  text "OTHER" at 13308.46,3085.44 h60
  text "SOLDER RESIST COLOR:" at 11484.68,3074.64 h60
  text "X" at 12563.42,2915.44 h60
  text "MATTE" at 12690.46,2915.44 h60
  text "SEMI-GLOSS" at 13308,2914.8 h60
  text "IMMERSION GOLD (ENIG)" at 12390.46,2726.92 h60
  text "ENEPIG" at 13728,2723.64 h60
  text "SURFACE FINISH:" at 11329.46,2722.64 h60
  text "X" at 12203.51,2722.64 h60
  text "IMM. TIN/SILVER OR EQUIV" at 11659,2565.64 h60
  text "OTHER" at 13090.46,2565.64 h60
  text "ARRAY/PANEL:" at 11329.46,2386.64 h60
  text "CUT AND TRIM PER M1 BOARD OUTLINE" at 12390.46,2382.35 h60
  text "N.C. ROUTE" at 12390.46,2230.64 h60
  text "X" at 13069.46,2230.64 h60
  text "V. SCORE" at 13256.46,2230.64 h60
  text "CERTIFICATION:" at 11329.46,2093.64 h60
  text "MATERIALS AND WORKMANSHIP FOR ALL PCBS" at 12054.46,2093.64 h60
  text "TO MEET OR EXCEED THE REQUIREMENTS OF:" at 12054.46,1995.64 h60
  text "X" at 11680.96,1859.13 h60
  text "ANSI IPC-A-600F CLASS ->" at 11819.96,1859.13 h60
  text "X" at 13459.02,1859.13 h60
  text "2" at 13577.96,1859.14 h60
  text "1" at 13262.96,1857.64 h60
  text "3" at 13931.96,1857.64 h60
  text "X" at 12495.02,1699.64 h60
  text "RoHS" at 12631.96,1699.64 h60
  text "OTHER" at 13276.36,1699.64 h60
  text "PER ORDER" at 13673.42,1699.64 h60
  text "ALL BOARDS MUST MEET OR EXCEED UL94-V0 REQUIREMENTS." at 11357,1534 h60
  text "PCB MUST BEAR THE UL94V-0 UL REGISTERED MATERIAL ID NUMBER" at 11357,1414 h60
  text "ADDITIONAL REQUIREMENTS:" at 11329.46,1240.64 h60
  text "MICROSECTION:" at 11404.23,1125.64 h60
  text "YES" at 12309.96,1125.64 h60
  text "REQUIRED" at 13171.46,969.49 h60
  text "BARE BOARD ELEC. TEST:" at 11404.23,966.64 h60
  text "NONE" at 12709.96,966.64 h60
  text "X" at 13044.46,966.64 h60
  text "PER ORDER" at 13763.46,966.64 h60
  text ".Layer_Name" at 577,-858.49 h60
M11 Gerber Information:
  lines w10: -292,-930.17 6308,-930.17 ; -292,-726.83 6310,-726.83 ; -292,-523.5 -292,-1133.5 3713,-1133.5 6310,-1133.5 6310,-523.5 -291.5,-523.5 -291.5,-1133.5 1284,-1133.5 ; 2173,-1133.5 2173,-523.5 ; 3440,-726.83 3440,-523.5 ; 4280,-726.83 4280,-523.5 ; 4902,-1140 4902,-937.17
  text "ALL ARTWORK VIEWED FROM TOP SIDE" at -228.5,-655.67 h60
  text "BOARD #:" at 2248,-655.67 h60
  text ".PRJ_Number" at 2793.5,-655.67 h60
  text "REV:" at 3638,-655.67 h60
  text ".PCB_Rev" at 3929.5,-655.67 h60
  text "SVN REV:" at 4476,-655.67 h60
  text ".VersionControl_RevNumber" at 4982,-655.67 h60
  text "LAYER NAME =" at -228.5,-858.49 h60
  text "TID #:" at 2248,-859 h60
  text ".TID" at 2793.5,-859 h60
  text "PLOT NAME =" at -228.5,-1064.34 h60
  text ".plot_File_Name" at 577,-1064.34 h60
  text "GENERATED    :" at 2250,-1064.34 h60
  text ".Print_Date" at 3119.5,-1064.34 h60
  text ".Print_Time" at 3848.5,-1064.34 h60
  text "TEXAS INSTRUMENTS" at 5113,-1064.34 h60
M12 Stackup:
  drawing of 295 lines, arcs and shapes, not listed
  text "Layer" at 2670.88,3845.68 h60
  text "Name" at 3080.8,3845.68 h60
  text "Material" at 4020.54,3845.68 h60
  text "Thickness" at 4880.3,3845.68 h60
  text "Constant" at 5530.14,3845.68 h60
  text "Board Layer Stack" at 6100,3845.68 h60
  text "1" at 2670.88,3725.68 h60
  text "Top Overlay" at 3080.8,3725.68 h60
  text "2" at 2670.88,3605.68 h60
  text "Top Solder" at 3080.8,3605.68 h60
  text "Solder Resist" at 4020.54,3605.68 h60
  text "0.40mil" at 4880.3,3605.68 h60
  text "3.5" at 5530.14,3605.68 h60
  text "3" at 2670.88,3485.68 h60
  text "Top Layer" at 3080.8,3485.68 h60
  text "Copper" at 4020.54,3485.68 h60
  text "1.40mil" at 4880.3,3485.68 h60
  text "4" at 2670.88,3365.68 h60
  text "Dielectric 1" at 3080.8,3365.68 h60
  text "FR-4" at 4020.54,3365.68 h60
  text "8.00mil" at 4880.3,3365.68 h60
  text "4.2" at 5530.14,3365.68 h60
  text "5" at 2670.88,3245.68 h60
  text "Signal Layer 1" at 3080.8,3245.68 h60
  text "Copper" at 4020.54,3245.68 h60
  text "1.40mil" at 4880.3,3245.68 h60
  text "6" at 2670.88,3125.68 h60
  text "Dielectric 2" at 3080.8,3125.68 h60
  text "FR-4" at 4020.54,3125.68 h60
  text "40.00mil" at 4880.3,3125.68 h60
  text "4.2" at 5530.14,3125.68 h60
  text "7" at 2670.88,3005.68 h60
  text "Signal Layer 2" at 3080.8,3005.68 h60
  text "Copper" at 4020.54,3005.68 h60
  text "1.40mil" at 4880.3,3005.68 h60
  text "8" at 2670.88,2885.68 h60
  text "Dielectric 3" at 3080.8,2885.68 h60
  text "FR-4" at 4020.54,2885.68 h60
  text "8.00mil" at 4880.3,2885.68 h60
  text "4.2" at 5530.14,2885.68 h60
  text "9" at 2670.88,2765.68 h60
  text "Bottom Layer" at 3080.8,2765.68 h60
  text "Copper" at 4020.54,2765.68 h60
  text "1.40mil" at 4880.3,2765.68 h60
  text "10" at 2670.88,2645.68 h60
  text "Bottom Solder" at 3080.8,2645.68 h60
  text "Solder Resist" at 4020.54,2645.68 h60
  text "0.40mil" at 4880.3,2645.68 h60
  text "3.5" at 5530.14,2645.68 h60
  text "11" at 2670.88,2525.68 h60
  text "Bottom Overlay" at 3080.8,2525.68 h60
  text ".Layer_Name" at 577,-858.49 h60
M13 Component Bodies Top:
  text ".Layer_Name" at 577,-858.49 h60
M14 Component Bodies Bottom:
  text ".Layer_Name" at 577,-858.49 h60
M15 Courtyards Top:
  text ".Layer_Name" at 577,-858.49 h60
M16 Courtyards Bottom:
  text ".Layer_Name" at 577,-858.49 h60
Drill Drawing:
  lines w10: 4910.65,1516.52 4932.72,1527.55 4954.79,1516.52 4943.75,1538.59 4954.79,1560.66 4932.72,1549.62 4910.65,1560.66 4921.68,1538.59 4910.65,1516.52 ; 4910.65,1626.87 4921.68,1626.87 4921.68,1615.84 4943.75,1615.84 4943.75,1626.87 4954.79,1626.87 4954.79,1648.94 4943.75,1648.94 4943.75,1659.98 4921.68,1659.98 4921.68,1648.94 4910.65,1648.94 4910.65,1626.87 ; 4910.65,1726.19 4921.68,1726.19 4932.72,1715.16 4943.75,1726.19 4954.79,1726.19 4943.75,1737.23 4954.79,1748.26 4943.75,1748.26 4932.72,1759.3 4921.68,1748.26 4910.65,1748.26 4921.68,1737.23 4910.65,1726.19
  lines w12: 4870,1486.72 7981.21,1486.72 ; 4870,1784.68 7981.21,1784.68 ; 5185.49,1387.4 5185.49,1884 ; 5502.58,1387.4 5502.58,1884 ; 6124.22,1387.4 6124.22,1884 ; 6368.41,1387.4 6368.41,1884 ; 6728.66,1387.4 6728.66,1884 ; 7437.12,1387.4 7437.12,1884 ; 4870,1387.4 7981.21,1387.4 7981.21,1884 4870,1884 4870,1387.4
  text "Symbol" at 4929.59,1814.48 h72
  text "Quantity" at 5215.28,1814.48 h72
  text "Finished Hole Size" at 5532.38,1814.48 h72
  text "Plated" at 6154.02,1814.48 h72
  text "Hole Type" at 6398.21,1814.48 h72
  text "Drill Layer Pair" at 6758.45,1814.48 h72
  text "Hole Tolerance" at 7466.92,1814.48 h72
  text "6" at 5215.28,1715.16 h60
  text "7.87mil (0.200mm)" at 5532.38,1715.16 h60
  text "PTH" at 6154.02,1715.16 h60
  text "Round" at 6398.21,1715.16 h60
  text "Top Layer - Bottom Layer" at 6758.45,1715.16 h60
  text "157" at 5215.28,1615.84 h60
  text "10.00mil (0.254mm)" at 5532.38,1615.84 h60
  text "PTH" at 6154.02,1615.84 h60
  text "Round" at 6398.21,1615.84 h60
  text "Top Layer - Bottom Layer" at 6758.45,1615.84 h60
  text "9" at 5215.28,1516.52 h60
  text "98.43mil (2.500mm)" at 5532.38,1516.52 h60
  text "PTH" at 6154.02,1516.52 h60
  text "Round" at 6398.21,1516.52 h60
  text "Top Layer - Bottom Layer" at 6758.45,1516.52 h60
  text "172 Total" at 5215.28,1417.2 h60
  text ".Layer_Name" at 577,-858.49 h60
Mechanical 17:
  text ".Layer_Name" at 577,-858.49 h60
Mechanical 18:
  text ".Layer_Name" at 577,-858.49 h60
Mechanical 19:
  text ".Layer_Name" at 577,-858.49 h60

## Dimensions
0,0 to 1539,0 on M2 Board Dimensions
0,0 to 0,1310 on M2 Board Dimensions
0,-400 to 1000,-400 on M2 Board Dimensions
